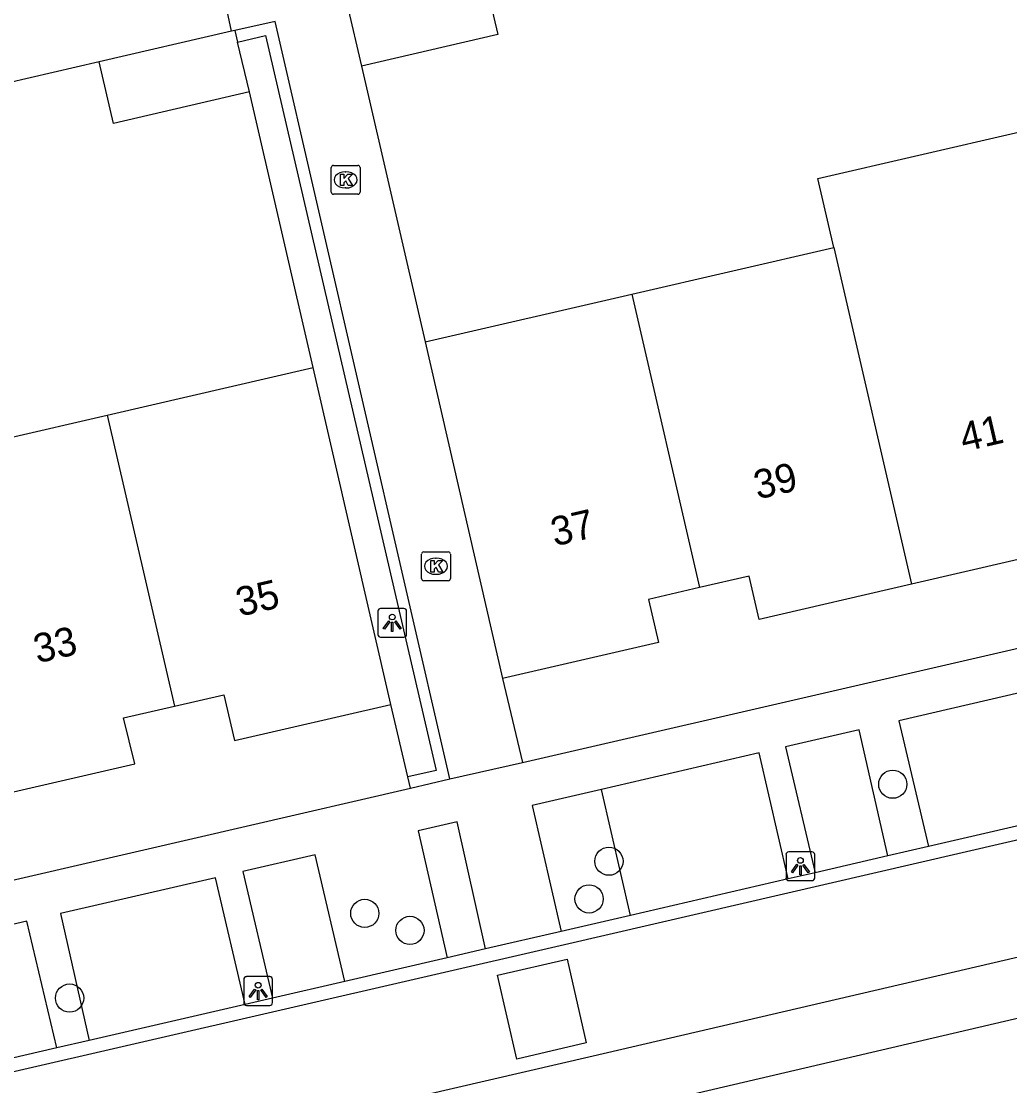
# Model space of a CAD drawing. Extents: x 156414 to 157775, y 382335 to 383765.
# Drawn here: x 156836.53 to 156870.84, y 382831.88 to 382868.83 of the extents above; entities that cross this region are included whole.
import ezdxf

# ---------------------------------------------------------------- set-up
doc = ezdxf.new("R2010")
doc.units = 0
for name, color, linetype in [('IMGEO_Boom', 7, 'Continuous'), ('IMGEO_Groenvoorziening', 7, 'Continuous'), ('IMGEO_Kolk', 7, 'Continuous'), ('IMGEO_Lichtpunt', 7, 'Continuous'), ('IMGEO_Muur', 7, 'Continuous'), ('IMGEO_Pand', 7, 'Continuous'), ('IMGEO_Pand_nummerreeks', 7, 'Continuous'), ('IMGEO_Rijbaan_lokaal_gesloten', 7, 'Continuous'), ('IMGEO_Rijbaan_lokaal_open', 7, 'Continuous'), ('IMGEO_Voetpad_open', 7, 'Continuous')]:
    doc.layers.add(name, color=color, linetype=linetype)

msp = doc.modelspace()

# ---------------------------------------------------------------- linework, layer by layer
at = {"layer": 'IMGEO_Boom'}
for centre in [(156866.782, 382842.344), (156856.928, 382839.67), (156856.237, 382838.362), (156848.452, 382837.861), (156850.02, 382837.269), (156838.204, 382834.92)]:
    msp.add_circle(centre, 0.489, dxfattribs=at)
at = {"layer": 'IMGEO_Groenvoorziening'}
for points in [[(156846.661, 382856.807), (156844.444, 382866.375)], [(156849.947, 382842.597), (156849.359, 382845.112)]]:
    msp.add_lwpolyline(points, dxfattribs=at)
at = {"layer": 'IMGEO_Kolk'}
for p, q in [((156847.36, 382863.824), (156848.212, 382863.824)), ((156847.285, 382862.898), (156847.285, 382863.75)), ((156847.773, 382863.604), (156847.798, 382863.604)), ((156848.286, 382863.75), (156848.286, 382862.898)), ((156848.212, 382862.824), (156847.36, 382862.824)), ((156847.796, 382863.044), (156847.771, 382863.044)), ((156850.421, 382849.484), (156850.421, 382850.336)), ((156850.496, 382850.41), (156851.348, 382850.41)), ((156850.909, 382850.19), (156850.934, 382850.19)), ((156851.422, 382850.336), (156851.422, 382849.484)), ((156851.348, 382849.41), (156850.496, 382849.41)), ((156850.932, 382849.63), (156850.907, 382849.63))]:
    msp.add_line(p, q, dxfattribs=at)
for points in [[(156847.36, 382863.824), (156848.212, 382863.824)], [(156847.285, 382862.898), (156847.285, 382863.75)], [(156847.606, 382863.524), (156847.729, 382863.524), (156847.729, 382863.373), (156847.859, 382863.524), (156848.023, 382863.524), (156847.877, 382863.373), (156848.03, 382863.124), (156847.878, 382863.124), (156847.793, 382863.288), (156847.729, 382863.221), (156847.729, 382863.124), (156847.606, 382863.124), (156847.606, 382863.524)], [(156848.286, 382863.75), (156848.286, 382862.898)], [(156848.212, 382862.824), (156847.36, 382862.824)], [(156850.421, 382849.484), (156850.421, 382850.336)], [(156850.496, 382850.41), (156851.348, 382850.41)], [(156851.422, 382850.336), (156851.422, 382849.484)], [(156850.742, 382850.11), (156850.865, 382850.11), (156850.865, 382849.959), (156850.995, 382850.11), (156851.159, 382850.11), (156851.013, 382849.959), (156851.166, 382849.71), (156851.014, 382849.71), (156850.929, 382849.874), (156850.865, 382849.807), (156850.865, 382849.71), (156850.742, 382849.71), (156850.742, 382850.11)], [(156851.348, 382849.41), (156850.496, 382849.41)]]:
    msp.add_lwpolyline(points, dxfattribs=at)
for centre, start, end in [((156847.362, 382863.748), 91.552, 178.448), ((156847.362, 382863.748), 91.552, 178.448), ((156848.21, 382863.748), 1.552, 88.448), ((156848.21, 382863.748), 1.552, 88.448), ((156847.362, 382862.9), 181.552, 268.448), ((156847.362, 382862.9), 181.552, 268.448), ((156848.21, 382862.9), 271.552, 358.448), ((156848.21, 382862.9), 271.552, 358.448), ((156850.498, 382850.334), 91.552, 178.448), ((156850.498, 382850.334), 91.552, 178.448), ((156851.346, 382850.334), 1.552, 88.448), ((156851.346, 382850.334), 1.552, 88.448), ((156850.498, 382849.486), 181.552, 268.448), ((156850.498, 382849.486), 181.552, 268.448), ((156851.346, 382849.486), 271.552, 358.448), ((156851.346, 382849.486), 271.552, 358.448)]:
    msp.add_arc(centre, 0.0765, start, end, dxfattribs=at)
for centre, major_axis, ratio, start_param, end_param in [((156847.772, 382863.324), (-0.387, 0.002), 0.722429, 4.712389, 7.853982), ((156847.797, 382863.324), (-0.39, 0.002), 0.717154, 1.570796, 4.712389), ((156850.908, 382849.91), (-0.387, 0.002), 0.722429, 4.712389, 7.853982), ((156850.933, 382849.91), (-0.39, 0.002), 0.717154, 1.570796, 4.712389)]:
    msp.add_ellipse(centre, major_axis=major_axis, ratio=ratio, start_param=start_param, end_param=end_param, dxfattribs=at)
at = {"layer": 'IMGEO_Lichtpunt'}
for p, q in [((156848.907, 382848.35), (156848.907, 382847.543)), ((156848.907, 382848.35), (156848.907, 382847.543)), ((156849.809, 382848.445), (156849.001, 382848.445)), ((156849.809, 382848.445), (156849.001, 382848.445)), ((156849.903, 382847.543), (156849.903, 382848.35)), ((156849.903, 382847.543), (156849.903, 382848.35)), ((156849.001, 382847.449), (156849.809, 382847.449)), ((156849.001, 382847.449), (156849.809, 382847.449)), ((156863.075, 382839.899), (156863.075, 382839.092)), ((156863.075, 382839.899), (156863.075, 382839.092)), ((156863.977, 382839.994), (156863.169, 382839.994)), ((156863.977, 382839.994), (156863.169, 382839.994)), ((156864.071, 382839.092), (156864.071, 382839.899)), ((156864.071, 382839.092), (156864.071, 382839.899)), ((156863.169, 382838.998), (156863.977, 382838.998)), ((156863.169, 382838.998), (156863.977, 382838.998)), ((156844.251, 382835.568), (156844.251, 382834.761)), ((156844.251, 382835.568), (156844.251, 382834.761)), ((156845.153, 382835.663), (156844.345, 382835.663)), ((156845.153, 382835.663), (156844.345, 382835.663)), ((156845.247, 382834.761), (156845.247, 382835.568)), ((156845.247, 382834.761), (156845.247, 382835.568)), ((156844.345, 382834.667), (156845.153, 382834.667)), ((156844.345, 382834.667), (156845.153, 382834.667))]:
    msp.add_line(p, q, dxfattribs=at)
for points in [[(156849.281, 382848.014), (156849.32, 382847.986), (156849.132, 382847.724), (156849.094, 382847.751), (156849.281, 382848.014)], [(156849.383, 382847.966), (156849.43, 382847.966), (156849.43, 382847.644), (156849.383, 382847.644), (156849.383, 382847.966)], [(156849.493, 382847.986), (156849.531, 382848.013), (156849.718, 382847.751), (156849.679, 382847.723), (156849.493, 382847.986)], [(156863.449, 382839.563), (156863.488, 382839.535), (156863.3, 382839.273), (156863.262, 382839.3), (156863.449, 382839.563)], [(156863.551, 382839.515), (156863.598, 382839.515), (156863.598, 382839.193), (156863.551, 382839.193), (156863.551, 382839.515)], [(156863.661, 382839.535), (156863.699, 382839.562), (156863.886, 382839.3), (156863.847, 382839.272), (156863.661, 382839.535)], [(156844.625, 382835.232), (156844.664, 382835.204), (156844.476, 382834.942), (156844.438, 382834.969), (156844.625, 382835.232)], [(156844.727, 382835.184), (156844.774, 382835.184), (156844.774, 382834.862), (156844.727, 382834.862), (156844.727, 382835.184)], [(156844.837, 382835.204), (156844.875, 382835.231), (156845.062, 382834.969), (156845.023, 382834.941), (156844.837, 382835.204)]]:
    msp.add_lwpolyline(points, dxfattribs=at)
for centre in [(156849.406, 382848.148), (156863.574, 382839.697), (156844.75, 382835.366)]:
    msp.add_circle(centre, 0.0994, dxfattribs=at)
for centre, start, end in [((156849.001, 382848.35), 90, 180), ((156849.001, 382848.35), 90, 180), ((156849.809, 382848.35), 0, 90), ((156849.809, 382848.35), 0, 90), ((156849.001, 382847.543), 180, 270), ((156849.001, 382847.543), 180, 270), ((156849.809, 382847.543), 270, 0), ((156849.809, 382847.543), 270, 360), ((156863.169, 382839.899), 90, 180), ((156863.169, 382839.899), 90, 180), ((156863.977, 382839.899), 0, 90), ((156863.977, 382839.899), 0, 90), ((156863.169, 382839.092), 180, 270), ((156863.169, 382839.092), 180, 270), ((156863.977, 382839.092), 270, 0), ((156863.977, 382839.092), 270, 360), ((156844.345, 382835.568), 90, 180), ((156844.345, 382835.568), 90, 180), ((156845.153, 382835.568), 0, 90), ((156845.153, 382835.568), 0, 90), ((156844.345, 382834.761), 180, 270), ((156844.345, 382834.761), 180, 270), ((156845.153, 382834.761), 270, 0), ((156845.153, 382834.761), 270, 360)]:
    msp.add_arc(centre, 0.0946, start, end, dxfattribs=at)
at = {"layer": 'IMGEO_Muur'}
for points in [[(156851.402, 382842.527), (156845.338, 382868.823), (156843.942, 382868.51)], [(156844.036, 382868.109), (156845.006, 382868.331), (156850.932, 382842.818), (156849.947, 382842.597)], [(156848.333, 382867.271), (156850.545, 382857.701)], [(156850.038, 382842.208), (156849.947, 382842.597)], [(156850.038, 382842.208), (156851.402, 382842.527)]]:
    msp.add_lwpolyline(points, dxfattribs=at)
at = {"layer": 'IMGEO_Pand'}
for points in [[(156852.577, 382870.491), (156853.068, 382868.367), (156848.333, 382867.271)], [(156847.84, 382869.397), (156848.333, 382867.271)], [(156843.826, 382868.491), (156839.228, 382867.427)], [(156843.942, 382868.51), (156843.826, 382868.491)], [(156843.942, 382868.51), (156844.036, 382868.109)], [(156844.444, 382866.375), (156844.036, 382868.109)], [(156844.444, 382866.375), (156839.724, 382865.284), (156839.228, 382867.427)], [(156864.73, 382860.979), (156864.176, 382863.373), (156871.189, 382864.996), (156871.744, 382862.599)], [(156857.717, 382859.358), (156864.73, 382860.979)], [(156864.73, 382860.979), (156867.434, 382849.292)], [(156850.545, 382857.701), (156857.717, 382859.358)], [(156857.717, 382859.358), (156860.074, 382849.17)], [(156850.545, 382857.701), (156853.238, 382846.009)], [(156839.503, 382855.153), (156846.661, 382856.807)], [(156849.359, 382845.112), (156846.661, 382856.807)], [(156832.488, 382853.532), (156839.503, 382855.153)], [(156839.503, 382855.153), (156841.846, 382845.058)], [(156874.101, 382852.413), (156872.343, 382852.01), (156872.69, 382850.509), (156867.434, 382849.292)], [(156867.434, 382849.292), (156862.139, 382848.066), (156861.791, 382849.566), (156860.074, 382849.17)], [(156860.074, 382849.17), (156858.303, 382848.762), (156858.65, 382847.262), (156853.238, 382846.009)], [(156841.846, 382845.058), (156843.561, 382845.452), (156843.926, 382843.863), (156849.359, 382845.112)], [(156835.19, 382841.839), (156840.466, 382843.057), (156840.072, 382844.65), (156841.846, 382845.058)]]:
    msp.add_lwpolyline(points, dxfattribs=at)
at = {"layer": 'IMGEO_Rijbaan_lokaal_gesloten'}
for points in [[(156704.67, 382802.003), (156706.623, 382802.451), (156776.982, 382818.697), (156816.178, 382827.739), (156855.39, 382836.785), (156925.817, 382853.068)], [(156926.664, 382849.268), (156923.197, 382848.454), (156856.378, 382832.904), (156817.084, 382823.811), (156780.281, 382815.295), (156707.464, 382798.538)]]:
    msp.add_lwpolyline(points, dxfattribs=at)
at = {"layer": 'IMGEO_Rijbaan_lokaal_open'}
for points in [[(156872.882, 382841.306), (156868.022, 382840.183)], [(156868.022, 382840.183), (156866.612, 382839.857)], [(156866.612, 382839.857), (156864.083, 382839.272)], [(156864.083, 382839.272), (156863.148, 382839.056)], [(156863.148, 382839.056), (156857.678, 382837.791)], [(156857.678, 382837.791), (156855.267, 382837.234)], [(156855.267, 382837.234), (156852.648, 382836.629)], [(156852.648, 382836.629), (156851.309, 382836.32)], [(156851.309, 382836.32), (156847.754, 382835.499)], [(156853.064, 382835.711), (156855.479, 382836.274), (156856.141, 382833.365), (156853.725, 382832.8), (156853.064, 382835.711)], [(156847.754, 382835.499), (156845.248, 382834.92)], [(156844.295, 382834.7), (156838.879, 382833.449)], [(156845.248, 382834.92), (156844.295, 382834.7)], [(156837.763, 382833.191), (156832.824, 382832.05)], [(156838.879, 382833.449), (156837.763, 382833.191)]]:
    msp.add_lwpolyline(points, dxfattribs=at)
at = {"layer": 'IMGEO_Voetpad_open'}
for points in [[(156843.826, 382868.491), (156843.397, 382870.5)], [(156839.228, 382867.427), (156834.426, 382866.316)], [(156848.333, 382867.271), (156850.545, 382857.701)], [(156853.925, 382843.103), (156924.352, 382859.349)], [(156856.714, 382830.844), (156856.91, 382830.891), (156859.126, 382831.425), (156927.114, 382847.315)], [(156853.238, 382846.009), (156853.925, 382843.103)], [(156872.882, 382841.306), (156871.879, 382845.68), (156866.991, 382844.55), (156868.022, 382840.183)], [(156866.612, 382839.857), (156865.613, 382844.232), (156863.056, 382843.641), (156864.083, 382839.272)], [(156863.148, 382839.056), (156862.147, 382843.431), (156856.667, 382842.164)], [(156851.402, 382842.527), (156853.925, 382843.103)], [(156726.991, 382813.763), (156728.366, 382814.072), (156850.038, 382842.208)], [(156856.667, 382842.164), (156854.267, 382841.609), (156855.267, 382837.234)], [(156857.678, 382837.791), (156856.667, 382842.164)], [(156852.648, 382836.629), (156851.654, 382841.037), (156850.308, 382840.726), (156851.309, 382836.32)], [(156847.754, 382835.499), (156846.725, 382839.898), (156844.218, 382839.319), (156845.248, 382834.92)], [(156844.295, 382834.7), (156843.264, 382839.098), (156837.886, 382837.855), (156838.879, 382833.449)], [(156837.763, 382833.191), (156836.719, 382837.586), (156831.751, 382836.438), (156832.824, 382832.05)]]:
    msp.add_lwpolyline(points, dxfattribs=at)

# ---------------------------------------------------------------- texts
at = {"layer": 'IMGEO_Pand_nummerreeks'}
for s, rotation, p in [('41', 13.0105, (156869.242, 382853.879)), ('39', 13.0105, (156862.087, 382852.226)), ('37', 13.0105, (156855.041, 382850.598)), ('35', 13.0041, (156844.107, 382848.159)), ('33', 13.0041, (156837.082, 382846.537))]:
    msp.add_text(s, height=1, rotation=rotation, dxfattribs=at).set_placement(p)

doc.saveas('drawing.dxf')
